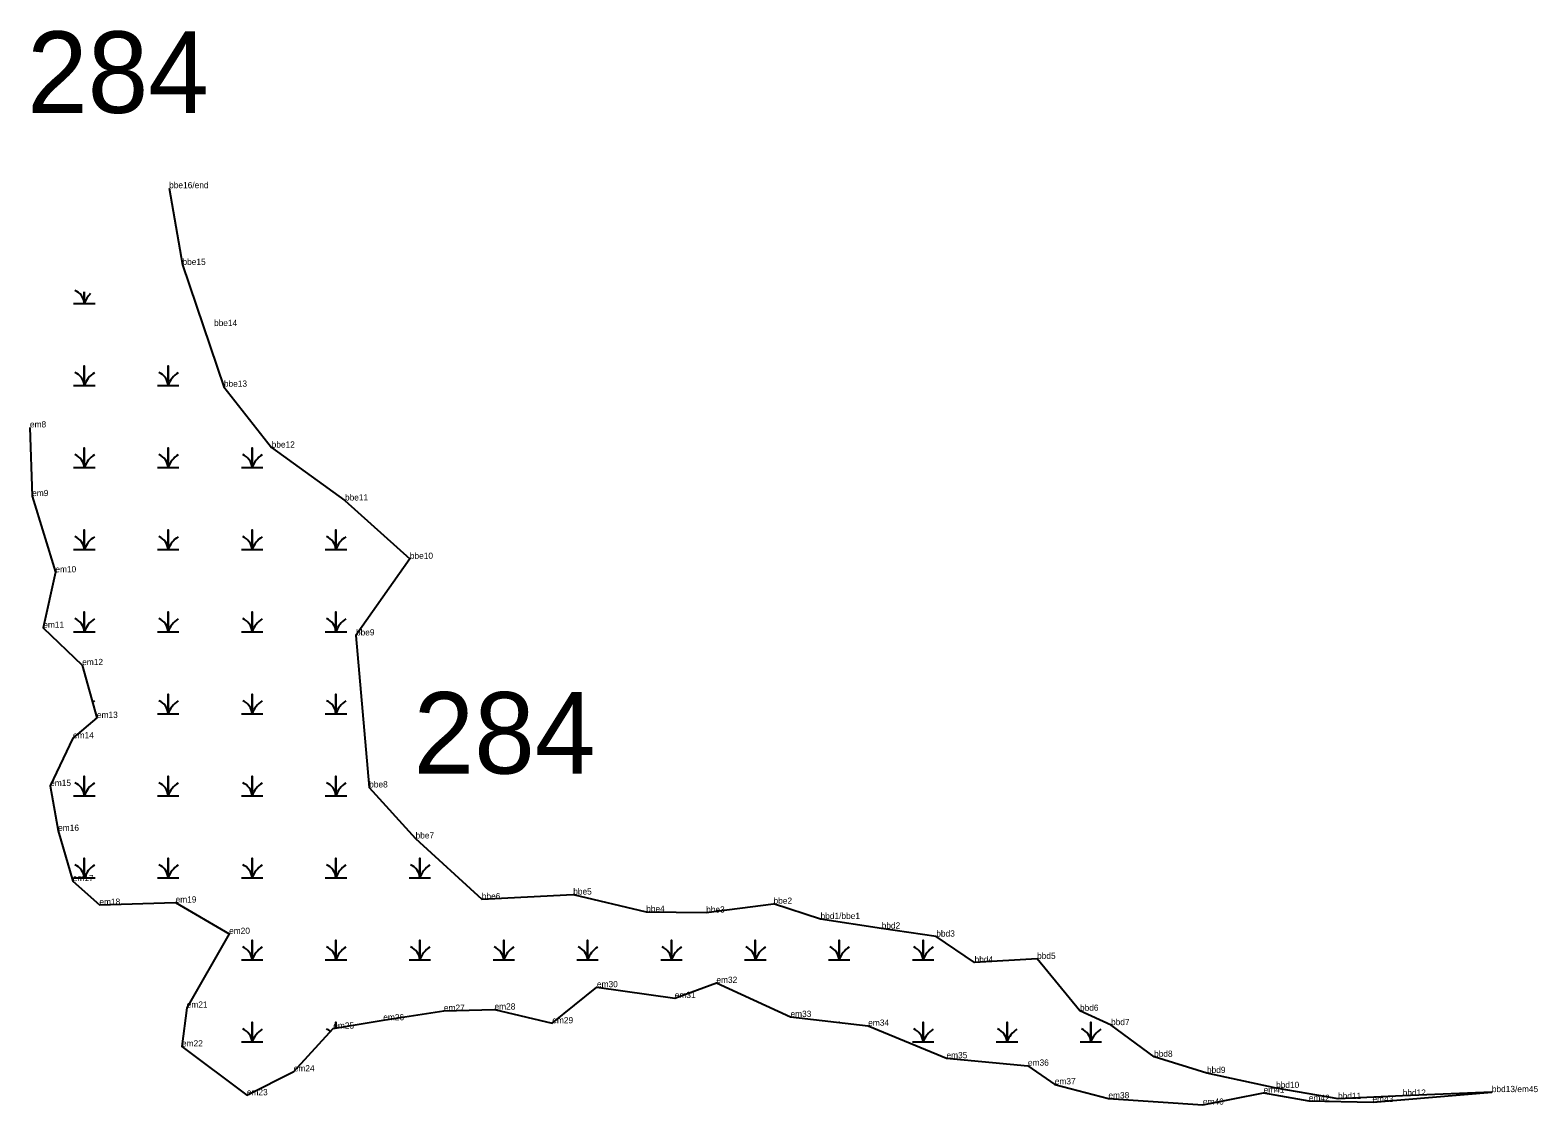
# Model space of a CAD drawing. Extents: x 2072529 to 2268796, y 436423 to 470397.
# Drawn here: x 2244941 to 2246149, y 440549 to 441411 of the extents above; entities that cross this region are included whole.
import ezdxf

# ---------------------------------------------------------------- set-up
doc = ezdxf.new("R2010")
doc.units = 0
for name, color, linetype in [('Default', 7, 'Continuous'), ('Exist Environmental Wetland Boundary', 7, 'Continuous'), ('Exist Environmental Wetland Boundary Cogo Comment', 7, 'Continuous'), ('Exist Environmental Wetland Boundary Cogo Point CELL', 7, 'Continuous'), ('Exist Hydro Swamp or Marsh', 7, 'Continuous')]:
    doc.layers.add(name, color=color, linetype=linetype)

msp = doc.modelspace()

# ---------------------------------------------------------------- linework, layer by layer
at = {"layer": 'Exist Environmental Wetland Boundary'}
for points in [[(2245052, 441283.8), (2245062.7, 441222.3), (2245095.9, 441124.6), (2245134.2, 441075.8), (2245193, 441033.4), (2245245, 440986.6), (2245201.8, 440925.2), (2245212.4, 440803.3), (2245249.6, 440762.4), (2245302.7, 440713.6), (2245376, 440717.4), (2245434.5, 440703.6), (2245482.6, 440703), (2245536.6, 440710)], [(2244940.4, 441092), (2244942.2, 441036.9), (2244960.8, 440975.8), (2244951.1, 440931.3), (2244982.3, 440901.4), (2244994.1, 440859.1), (2244974.9, 440842.7), (2244956.6, 440804.5), (2244963, 440768.5), (2244974.7, 440728.2), (2244996.1, 440709.2), (2245057.2, 440711), (2245100.1, 440685.9), (2245066.1, 440626.7), (2245062.3, 440595.6), (2245114.3, 440556.5), (2245151.9, 440575.6), (2245183.6, 440609.9), (2245223.7, 440616.6), (2245272.3, 440624.2), (2245312.9, 440625.2), (2245359.2, 440614.2), (2245395, 440643.1), (2245457.4, 440634.4), (2245490.8, 440646.6), (2245550.2, 440619.3), (2245612.5, 440612.2), (2245675.3, 440586.1), (2245740.6, 440580.2), (2245762.1, 440565.2), (2245805.1, 440554), (2245880.9, 440548.9), (2245929.5, 440558.5), (2245965.8, 440551.9), (2246017.3, 440551), (2246112.5, 440559), (2246041, 440556.1), (2245989.2, 440553.5), (2245939.5, 440562.3), (2245884.1, 440574.3), (2245841.7, 440587.3), (2245807.2, 440612.7), (2245782.3, 440624.2), (2245747.9, 440665.8), (2245697.8, 440663), (2245667.1, 440683.7), (2245623.3, 440690.1), (2245574.3, 440697.8), (2245536.6, 440710)]]:
    msp.add_lwpolyline(points, dxfattribs=at)
at = {"layer": 'Exist Environmental Wetland Boundary Cogo Point CELL'}
for p, q in [((2245052, 441283.8), (2245052, 441283.8)), ((2245062.7, 441222.3), (2245062.7, 441222.3)), ((2245088, 441173.3), (2245088, 441173.3)), ((2245095.9, 441124.6), (2245095.9, 441124.6)), ((2245134.2, 441075.8), (2245134.2, 441075.8)), ((2244942.2, 441036.9), (2244942.2, 441036.9)), ((2245193, 441033.4), (2245193, 441033.4)), ((2245245, 440986.6), (2245245, 440986.6)), ((2244960.8, 440975.8), (2244960.8, 440975.8)), ((2244951.1, 440931.3), (2244951.1, 440931.3)), ((2245201.8, 440925.2), (2245201.8, 440925.2)), ((2244982.3, 440901.4), (2244982.3, 440901.4)), ((2244994.1, 440859.1), (2244994.1, 440859.1)), ((2244974.9, 440842.7), (2244974.9, 440842.7)), ((2244956.6, 440804.5), (2244956.6, 440804.5)), ((2245212.4, 440803.3), (2245212.4, 440803.3)), ((2244963, 440768.5), (2244963, 440768.5)), ((2245249.6, 440762.4), (2245249.6, 440762.4)), ((2244974.7, 440728.2), (2244974.7, 440728.2)), ((2245376, 440717.4), (2245376, 440717.4)), ((2244996.1, 440709.2), (2244996.1, 440709.2)), ((2245057.2, 440711), (2245057.2, 440711)), ((2245302.7, 440713.6), (2245302.7, 440713.6)), ((2245434.5, 440703.6), (2245434.5, 440703.6)), ((2245482.6, 440703), (2245482.6, 440703)), ((2245536.6, 440710), (2245536.6, 440710)), ((2245574.3, 440697.8), (2245574.3, 440697.8)), ((2245623.3, 440690.1), (2245623.3, 440690.1)), ((2245100.1, 440685.9), (2245100.1, 440685.9)), ((2245667.1, 440683.7), (2245667.1, 440683.7)), ((2245747.9, 440665.8), (2245747.9, 440665.8)), ((2245697.8, 440663), (2245697.8, 440663)), ((2245395, 440643.1), (2245395, 440643.1)), ((2245490.8, 440646.6), (2245490.8, 440646.6)), ((2245457.4, 440634.4), (2245457.4, 440634.4)), ((2245066.1, 440626.7), (2245066.1, 440626.7)), ((2245272.3, 440624.2), (2245272.3, 440624.2)), ((2245312.9, 440625.2), (2245312.9, 440625.2)), ((2245550.2, 440619.3), (2245550.2, 440619.3)), ((2245782.3, 440624.2), (2245782.3, 440624.2)), ((2245183.6, 440609.9), (2245183.6, 440609.9)), ((2245223.7, 440616.6), (2245223.7, 440616.6)), ((2245359.2, 440614.2), (2245359.2, 440614.2)), ((2245612.5, 440612.2), (2245612.5, 440612.2)), ((2245807.2, 440612.7), (2245807.2, 440612.7)), ((2245062.3, 440595.6), (2245062.3, 440595.6)), ((2245675.3, 440586.1), (2245675.3, 440586.1)), ((2245841.7, 440587.3), (2245841.7, 440587.3)), ((2245151.9, 440575.6), (2245151.9, 440575.6)), ((2245740.6, 440580.2), (2245740.6, 440580.2)), ((2245884.1, 440574.3), (2245884.1, 440574.3)), ((2245762.1, 440565.2), (2245762.1, 440565.2)), ((2245929.5, 440558.5), (2245929.5, 440558.5)), ((2245939.5, 440562.3), (2245939.5, 440562.3)), ((2246112.5, 440559), (2246112.5, 440559)), ((2245114.3, 440556.5), (2245114.3, 440556.5)), ((2245805.1, 440554), (2245805.1, 440554)), ((2245880.9, 440548.9), (2245880.9, 440548.9)), ((2245967.4, 440552.2), (2245967.4, 440552.2)), ((2245989.2, 440553.5), (2245989.2, 440553.5)), ((2246017.3, 440551), (2246017.3, 440551)), ((2246041, 440556.2), (2246041, 440556.2))]:
    msp.add_line(p, q, dxfattribs=at)
at = {"layer": 'Exist Hydro Swamp or Marsh'}
for points in [[(2244975.4, 441191.4), (2244984, 441191.4), (2244984, 441200.6)], [(2244984, 441200.6), (2244984, 441191.4), (2244992.6, 441191.4)], [(2244975.4, 441125.6), (2244984, 441125.6), (2244984, 441141.4), (2244984, 441125.6), (2244992.6, 441125.6)], [(2245042.7, 441125.6), (2245051.3, 441125.6), (2245051.3, 441141.4), (2245051.3, 441125.6), (2245059.9, 441125.6)], [(2244975.4, 441059.8), (2244984, 441059.8), (2244984, 441075.6), (2244984, 441059.8), (2244992.6, 441059.8)], [(2245042.7, 441059.8), (2245051.3, 441059.8), (2245051.3, 441075.6), (2245051.3, 441059.8), (2245059.9, 441059.8)], [(2245109.9, 441059.8), (2245118.5, 441059.8), (2245118.5, 441075.6), (2245118.5, 441059.8), (2245127.1, 441059.8)], [(2244975.4, 440994), (2244984, 440994), (2244984, 441009.8), (2244984, 440994), (2244992.6, 440994)], [(2245042.7, 440994), (2245051.3, 440994), (2245051.3, 441009.8), (2245051.3, 440994), (2245059.9, 440994)], [(2245109.9, 440994), (2245118.5, 440994), (2245118.5, 441009.8), (2245118.5, 440994), (2245127.1, 440994)], [(2245177.2, 440994), (2245185.8, 440994), (2245185.8, 441009.8), (2245185.8, 440994), (2245194.4, 440994)], [(2244975.4, 440928.2), (2244984, 440928.2), (2244984, 440944), (2244984, 440928.2), (2244992.6, 440928.2)], [(2245042.7, 440928.2), (2245051.3, 440928.2), (2245051.3, 440944), (2245051.3, 440928.2), (2245059.9, 440928.2)], [(2245109.9, 440928.2), (2245118.5, 440928.2), (2245118.5, 440944), (2245118.5, 440928.2), (2245127.1, 440928.2)], [(2245177.2, 440928.2), (2245185.8, 440928.2), (2245185.8, 440944), (2245185.8, 440928.2), (2245194.4, 440928.2)], [(2245042.7, 440862.4), (2245051.3, 440862.4), (2245051.3, 440878.2), (2245051.3, 440862.4), (2245059.9, 440862.4)], [(2245109.9, 440862.4), (2245118.5, 440862.4), (2245118.5, 440878.2), (2245118.5, 440862.4), (2245127.1, 440862.4)], [(2245177.2, 440862.4), (2245185.8, 440862.4), (2245185.8, 440878.2), (2245185.8, 440862.4), (2245194.4, 440862.4)], [(2244975.4, 440796.6), (2244984, 440796.6), (2244984, 440812.4), (2244984, 440796.6), (2244992.6, 440796.6)], [(2245042.7, 440796.6), (2245051.3, 440796.6), (2245051.3, 440812.4), (2245051.3, 440796.6), (2245059.9, 440796.6)], [(2245109.9, 440796.6), (2245118.5, 440796.6), (2245118.5, 440812.4), (2245118.5, 440796.6), (2245127.1, 440796.6)], [(2245177.2, 440796.6), (2245185.8, 440796.6), (2245185.8, 440812.4), (2245185.8, 440796.6), (2245194.4, 440796.6)], [(2244975.4, 440730.8), (2244984, 440730.8), (2244984, 440746.6), (2244984, 440730.8), (2244992.6, 440730.8)], [(2245042.7, 440730.8), (2245051.3, 440730.8), (2245051.3, 440746.6), (2245051.3, 440730.8), (2245059.9, 440730.8)], [(2245109.9, 440730.8), (2245118.5, 440730.8), (2245118.5, 440746.6), (2245118.5, 440730.8), (2245127.1, 440730.8)], [(2245177.2, 440730.8), (2245185.8, 440730.8), (2245185.8, 440746.6), (2245185.8, 440730.8), (2245194.4, 440730.8)], [(2245244.4, 440730.8), (2245253, 440730.8), (2245253, 440746.6), (2245253, 440730.8), (2245261.6, 440730.8)], [(2245109.9, 440665), (2245118.5, 440665), (2245118.5, 440680.8), (2245118.5, 440665), (2245127.1, 440665)], [(2245177.2, 440665), (2245185.8, 440665), (2245185.8, 440680.8), (2245185.8, 440665), (2245194.4, 440665)], [(2245244.4, 440665), (2245253, 440665), (2245253, 440680.8), (2245253, 440665), (2245261.6, 440665)], [(2245311.7, 440665), (2245320.3, 440665), (2245320.3, 440680.8), (2245320.3, 440665), (2245328.9, 440665)], [(2245378.9, 440665), (2245387.5, 440665), (2245387.5, 440680.8), (2245387.5, 440665), (2245396.1, 440665)], [(2245446.2, 440665), (2245454.8, 440665), (2245454.8, 440680.8), (2245454.8, 440665), (2245463.4, 440665)], [(2245513.4, 440665), (2245522, 440665), (2245522, 440680.8), (2245522, 440665), (2245530.6, 440665)], [(2245580.7, 440665), (2245589.3, 440665), (2245589.3, 440680.8), (2245589.3, 440665), (2245597.9, 440665)], [(2245647.9, 440665), (2245656.5, 440665), (2245656.5, 440680.8), (2245656.5, 440665), (2245665.1, 440665)], [(2245109.9, 440599.2), (2245118.5, 440599.2), (2245118.5, 440615), (2245118.5, 440599.2), (2245127.1, 440599.2)], [(2245185.8, 440610.2), (2245185.8, 440615), (2245185.8, 440610.2)], [(2245589.3, 440614.8), (2245589.3, 440615), (2245589.3, 440614.8)], [(2245647.9, 440599.2), (2245656.5, 440599.2), (2245656.5, 440615), (2245656.5, 440599.2), (2245665.1, 440599.2)], [(2245715.2, 440599.2), (2245723.8, 440599.2), (2245723.8, 440615), (2245723.8, 440599.2), (2245732.4, 440599.2)], [(2245782.4, 440599.2), (2245791, 440599.2), (2245791, 440615), (2245791, 440599.2), (2245799.6, 440599.2)]]:
    msp.add_lwpolyline(points, dxfattribs=at)
for centre, radius, start, end in [((2244971.8, 441190.5), 12.3, 4.1403, 67.535), ((2245002.3, 441185.4), 19.2, 133.7641, 161.6222), ((2244971.8, 441124.7), 12.3, 4.1403, 67.535), ((2245002.3, 441119.6), 19.2, 122.1274, 161.6222), ((2245039, 441124.7), 12.3, 4.1403, 67.535), ((2245069.5, 441119.6), 19.2, 122.1274, 161.6222), ((2244971.8, 441058.9), 12.3, 4.1403, 67.535), ((2245002.3, 441053.8), 19.2, 122.1274, 161.6222), ((2245039, 441058.9), 12.3, 4.1403, 67.535), ((2245069.5, 441053.8), 19.2, 122.1274, 161.6222), ((2245106.3, 441058.9), 12.3, 4.1403, 67.535), ((2245136.8, 441053.8), 19.2, 122.1274, 161.6222), ((2244971.8, 440993.1), 12.3, 4.1403, 67.535), ((2245002.3, 440988), 19.2, 122.1274, 161.6222), ((2245039, 440993.1), 12.3, 4.1403, 67.535), ((2245069.5, 440988), 19.2, 122.1274, 161.6222), ((2245106.3, 440993.1), 12.3, 4.1403, 67.535), ((2245136.8, 440988), 19.2, 122.1274, 161.6222), ((2245173.5, 440993.1), 12.3, 4.1403, 67.535), ((2245204, 440988), 19.2, 122.1274, 161.6222), ((2244971.8, 440927.3), 12.3, 4.1403, 67.535), ((2245002.3, 440922.2), 19.2, 122.1274, 161.6222), ((2245039, 440927.3), 12.3, 4.1403, 67.535), ((2245069.5, 440922.2), 19.2, 122.1274, 161.6222), ((2245106.3, 440927.3), 12.3, 4.1403, 67.535), ((2245136.8, 440922.2), 19.2, 122.1274, 161.6222), ((2245173.5, 440927.3), 12.3, 4.1403, 67.535), ((2245204, 440922.2), 19.2, 122.1274, 161.6222), ((2245002.3, 440856.4), 19.2, 122.1274, 127.369), ((2245039, 440861.5), 12.3, 4.1403, 67.535), ((2245069.5, 440856.4), 19.2, 122.1274, 161.6222), ((2245106.3, 440861.5), 12.3, 4.1403, 67.535), ((2245136.8, 440856.4), 19.2, 122.1274, 161.6222), ((2245173.5, 440861.5), 12.3, 4.1403, 67.535), ((2245204, 440856.4), 19.2, 122.1274, 161.6222), ((2244971.8, 440795.7), 12.3, 4.1403, 67.535), ((2245002.3, 440790.6), 19.2, 122.1274, 161.6222), ((2245039, 440795.7), 12.3, 4.1403, 67.535), ((2245069.5, 440790.6), 19.2, 122.1274, 161.6222), ((2245106.3, 440795.7), 12.3, 4.1403, 67.535), ((2245136.8, 440790.6), 19.2, 122.1274, 161.6222), ((2245173.5, 440795.7), 12.3, 4.1403, 67.535), ((2245204, 440790.6), 19.2, 122.1274, 161.6222), ((2244971.8, 440729.9), 12.3, 4.1403, 67.535), ((2245002.3, 440724.8), 19.2, 122.1274, 161.6222), ((2245039, 440729.9), 12.3, 4.1403, 67.535), ((2245069.5, 440724.8), 19.2, 122.1274, 161.6222), ((2245106.3, 440729.9), 12.3, 4.1403, 67.535), ((2245136.8, 440724.8), 19.2, 122.1274, 161.6222), ((2245173.5, 440729.9), 12.3, 4.1403, 67.535), ((2245204, 440724.8), 19.2, 122.1274, 161.6222), ((2245240.8, 440729.9), 12.3, 4.1403, 67.535), ((2245271.3, 440724.8), 19.2, 122.1274, 161.6222), ((2245106.3, 440664.1), 12.3, 4.1403, 67.535), ((2245136.8, 440659), 19.2, 122.1274, 161.6222), ((2245173.5, 440664.1), 12.3, 4.1403, 67.535), ((2245204, 440659), 19.2, 122.1274, 161.6222), ((2245240.8, 440664.1), 12.3, 4.1403, 67.535), ((2245271.3, 440659), 19.2, 122.1274, 161.6222), ((2245308, 440664.1), 12.3, 4.1403, 67.535), ((2245338.5, 440659), 19.2, 122.1274, 161.6222), ((2245375.3, 440664.1), 12.3, 4.1403, 67.535), ((2245405.8, 440659), 19.2, 122.1274, 161.6222), ((2245442.5, 440664.1), 12.3, 4.1403, 67.535), ((2245473, 440659), 19.2, 122.1274, 161.6222), ((2245509.8, 440664.1), 12.3, 4.1403, 67.535), ((2245540.3, 440659), 19.2, 122.1274, 161.6222), ((2245577, 440664.1), 12.3, 4.1403, 67.535), ((2245607.5, 440659), 19.2, 122.1274, 161.6222), ((2245644.3, 440664.1), 12.3, 4.1403, 67.535), ((2245674.8, 440659), 19.2, 122.1274, 161.6222), ((2245106.3, 440598.3), 12.3, 4.1403, 67.535), ((2245136.8, 440593.2), 19.2, 122.1274, 161.6222), ((2245173.5, 440598.3), 12.3, 49.2168, 67.535), ((2245644.3, 440598.3), 12.3, 4.1403, 67.535), ((2245674.8, 440593.2), 19.2, 122.1274, 161.6222), ((2245711.5, 440598.3), 12.3, 4.1403, 67.535), ((2245742, 440593.2), 19.2, 122.1274, 161.6222), ((2245778.8, 440598.3), 12.3, 4.1403, 67.535), ((2245809.3, 440593.2), 19.2, 122.1274, 161.6222)]:
    msp.add_arc(centre, radius, start, end, dxfattribs=at)

# ---------------------------------------------------------------- texts
at = {"layer": 'Default'}
for p in [(2244938.1, 441344.2), (2245248, 440814.4)]:
    msp.add_text('284', height=65.34, dxfattribs=at).set_placement(p)
at = {"layer": 'Exist Environmental Wetland Boundary Cogo Comment'}
for s, p in [('bbe16/end', (2245052, 441283.8)), ('bbe15', (2245062.7, 441222.3)), ('bbe14', (2245088, 441173.3)), ('bbe13', (2245095.9, 441124.6)), ('em8', (2244940.4, 441092)), ('bbe12', (2245134.2, 441075.8)), ('em9', (2244942.2, 441036.9)), ('bbe11', (2245193, 441033.4)), ('em10', (2244960.8, 440975.8)), ('bbe10', (2245245, 440986.6)), ('em11', (2244951.1, 440931.3)), ('bbe9', (2245201.8, 440925.2)), ('em12', (2244982.3, 440901.4)), ('em13', (2244994.1, 440859.1)), ('em14', (2244974.9, 440842.7)), ('em15', (2244956.6, 440804.5)), ('bbe8', (2245212.4, 440803.3)), ('em16', (2244963, 440768.5)), ('bbe7', (2245249.6, 440762.4)), ('em17', (2244974.7, 440728.2)), ('em18', (2244996.1, 440709.2)), ('em19', (2245057.2, 440711)), ('bbe6', (2245302.7, 440713.6)), ('bbe5', (2245376, 440717.4)), ('bbe2', (2245536.6, 440710)), ('bbe4', (2245434.5, 440703.6)), ('bbe3', (2245482.6, 440703)), ('bbd1/bbe1', (2245574.3, 440697.8)), ('em20', (2245100.1, 440685.9)), ('bbd2', (2245623.3, 440690.1)), ('bbd3', (2245667.1, 440683.7)), ('bbd4', (2245697.8, 440663)), ('bbd5', (2245747.9, 440665.8)), ('em30', (2245395, 440643.1)), ('em32', (2245490.8, 440646.6)), ('em21', (2245066.1, 440626.7)), ('em28', (2245312.9, 440625.2)), ('em31', (2245457.4, 440634.4)), ('bbd6', (2245782.3, 440624.2)), ('em26', (2245223.7, 440616.6)), ('em27', (2245272.3, 440624.2)), ('em29', (2245359.2, 440614.2)), ('em33', (2245550.2, 440619.3)), ('bbd7', (2245807.2, 440612.7)), ('em25', (2245183.6, 440609.9)), ('em34', (2245612.5, 440612.2)), ('em22', (2245062.3, 440595.6)), ('em35', (2245675.3, 440586.1)), ('em36', (2245740.6, 440580.2)), ('bbd8', (2245841.7, 440587.3)), ('em24', (2245151.9, 440575.6)), ('em37', (2245762.1, 440565.2)), ('bbd9', (2245884.1, 440574.3)), ('em23', (2245114.3, 440556.5)), ('em38', (2245805.1, 440554)), ('em41', (2245929.5, 440558.5)), ('bbd10', (2245939.5, 440562.3)), ('em42', (2245965.8, 440551.9)), ('bbd11', (2245989.2, 440553.5)), ('bbd12', (2246041, 440556.1)), ('bbd13/em45', (2246112.5, 440559)), ('em40', (2245880.9, 440548.9)), ('em43', (2246016.8, 440551))]:
    msp.add_text(s, height=5, dxfattribs=at).set_placement(p)

doc.saveas('drawing.dxf')
